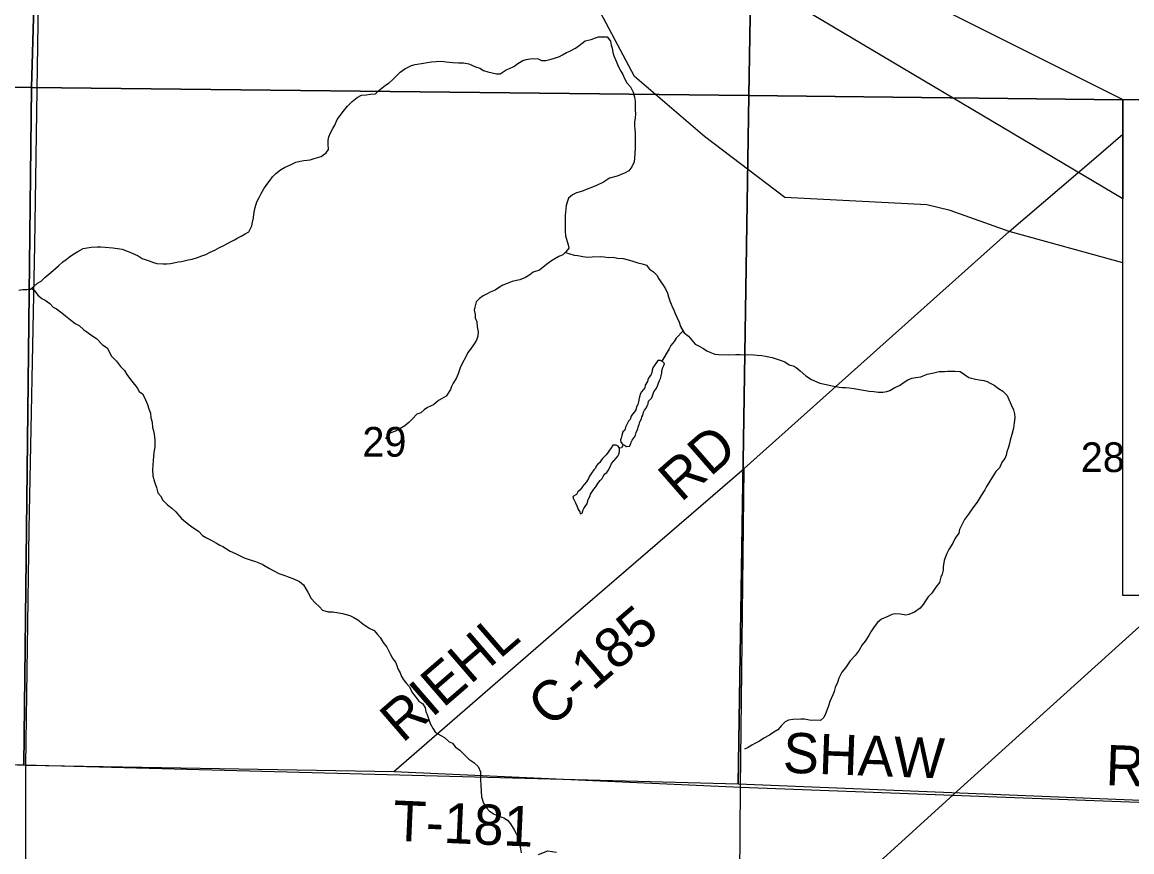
# Model space of a CAD drawing. Extents: x 0 to 34, y 0 to 22.
# Drawn here: x 26.932 to 28.499, y 14.843 to 16.014 of the extents above; entities that cross this region are included whole.
import ezdxf

# ---------------------------------------------------------------- set-up
doc = ezdxf.new("R2010")
doc.units = 0
for name, color, linetype in [('GM_X_County_Road', 7, 'Continuous'), ('GM_X_County_Road_Text', 7, 'Continuous'), ('GM_X_Minor_Lake', 7, 'Continuous'), ('GM_X_Minor_River', 7, 'Continuous'), ('GM_X_Rail_Line', 7, 'Continuous'), ('GM_X_Section', 7, 'Continuous'), ('GM_X_Section_Text', 7, 'Continuous'), ('GM_X_State_Route', 7, 'Continuous'), ('GM_X_Township_Road', 7, 'Continuous'), ('GM_X_Township_Road_Text', 7, 'Continuous'), ('SH_Data', 7, 'Continuous')]:
    doc.layers.add(name, color=color, linetype=linetype)

msp = doc.modelspace()

# ---------------------------------------------------------------- linework, layer by layer
at = {"layer": 'GM_X_County_Road'}
msp.add_line((26.9373, 14.9656), (27.457, 14.957), dxfattribs=at)
for points in [[(27.457, 14.957), (27.693, 15.1617), (27.9517, 15.3847), (28.3257, 15.7191), (28.4454, 15.8213), (28.4862, 15.8565)], [(25.9196, 14.987), (25.9277, 14.9881), (25.9453, 14.988), (26.0896, 14.9852), (26.5296, 14.9746), (26.8435, 14.9693), (26.9373, 14.9656)]]:
    msp.add_lwpolyline(points, dxfattribs=at)
at = {"layer": 'GM_X_Minor_Lake'}
for points in [[(27.8297, 15.5369), (27.8227, 15.5268), (27.8215, 15.5234), (27.8211, 15.52), (27.8199, 15.5162), (27.8171, 15.5128), (27.8156, 15.5098), (27.8151, 15.5072), (27.812, 15.5019), (27.8112, 15.4985), (27.8065, 15.4929), (27.8045, 15.4896), (27.8041, 15.4869), (27.8033, 15.4839), (27.8024, 15.4786), (27.8016, 15.4748), (27.7996, 15.4715), (27.7988, 15.4673), (27.7968, 15.4643), (27.7937, 15.4613), (27.7922, 15.4583), (27.7905, 15.4538), (27.7882, 15.4512), (27.7859, 15.4467), (27.7839, 15.4429), (27.783, 15.4388), (27.7803, 15.4362), (27.7787, 15.4309), (27.7779, 15.4275), (27.7771, 15.4249), (27.7774, 15.4215), (27.78, 15.4184), (27.7808, 15.4181)], [(27.7808, 15.4181), (27.7826, 15.4176), (27.7856, 15.4156), (27.7898, 15.4159), (27.7917, 15.4193), (27.7922, 15.4219), (27.7933, 15.4245), (27.7961, 15.4283), (27.798, 15.4317), (27.7992, 15.4351), (27.8012, 15.4403), (27.8021, 15.4433), (27.8033, 15.4467), (27.8041, 15.4505), (27.8065, 15.4546), (27.8069, 15.4573), (27.8085, 15.4599), (27.8093, 15.4641), (27.8109, 15.4667), (27.8132, 15.4697), (27.8148, 15.4731), (27.816, 15.4757), (27.8164, 15.4795), (27.8211, 15.4843), (27.8219, 15.4873), (27.8239, 15.4926), (27.827, 15.4963), (27.8294, 15.5005), (27.8302, 15.5039), (27.8322, 15.5087), (27.8334, 15.5114), (27.8342, 15.5152), (27.8351, 15.5197), (27.8355, 15.5223), (27.8367, 15.5269), (27.8383, 15.5299), (27.8391, 15.5329), (27.8365, 15.5352), (27.8332, 15.5368), (27.8297, 15.5369)], [(27.7663, 15.4175), (27.7636, 15.4138), (27.7616, 15.4104), (27.7585, 15.4063), (27.7566, 15.4037), (27.7515, 15.3984), (27.7492, 15.3955), (27.7476, 15.3928), (27.7449, 15.3906), (27.7426, 15.3876), (27.7414, 15.385), (27.7391, 15.3824), (27.736, 15.3779), (27.7332, 15.3738), (27.7316, 15.3704), (27.7289, 15.3655), (27.7258, 15.3618), (27.7231, 15.3592), (27.7219, 15.3566), (27.7196, 15.3539), (27.7169, 15.3517), (27.7149, 15.3476), (27.7095, 15.345), (27.7102, 15.3424), (27.7117, 15.3397), (27.7135, 15.3359), (27.7153, 15.332), (27.7164, 15.3293), (27.7171, 15.3267), (27.7193, 15.3232), (27.72, 15.3206), (27.7231, 15.322), (27.7239, 15.325), (27.7251, 15.328), (27.7278, 15.3322), (27.7298, 15.3348), (27.7314, 15.3408), (27.7334, 15.3449), (27.7346, 15.3483), (27.7393, 15.3551), (27.742, 15.3584), (27.7451, 15.3633), (27.7482, 15.3674), (27.751, 15.3704), (27.7525, 15.373), (27.7549, 15.3771), (27.7576, 15.379), (27.7595, 15.3816), (27.7627, 15.388), (27.7643, 15.3917), (27.7709, 15.3992), (27.7732, 15.4018), (27.7748, 15.4048), (27.7756, 15.4082), (27.7753, 15.413)], [(27.7753, 15.413), (27.7735, 15.4158), (27.7709, 15.4174), (27.7663, 15.4175)]]:
    msp.add_lwpolyline(points, dxfattribs=at)
at = {"layer": 'GM_X_Minor_River'}
for points in [[(27.2599, 15.7486), (27.2611, 15.7531), (27.2634, 15.7607), (27.2669, 15.7671), (27.2693, 15.7728), (27.2731, 15.7792), (27.2777, 15.7856), (27.282, 15.7916), (27.2855, 15.7961), (27.2904, 15.801), (27.2966, 15.8059), (27.3023, 15.8092), (27.3076, 15.8118), (27.3126, 15.8141), (27.3183, 15.8167), (27.3248, 15.8185), (27.3297, 15.8192), (27.3343, 15.8199), (27.3388, 15.8202), (27.3445, 15.8221), (27.3544, 15.825), (27.3613, 15.8303), (27.3648, 15.8348), (27.3641, 15.8424), (27.3642, 15.8481), (27.365, 15.8526), (27.3673, 15.8583), (27.3708, 15.8643), (27.3735, 15.8692), (27.3767, 15.8772), (27.387, 15.8907), (27.3913, 15.896), (27.3978, 15.9024), (27.4051, 15.9084), (27.4112, 15.9113), (27.418, 15.912), (27.4241, 15.9131), (27.4309, 15.9134), (27.4355, 15.9183), (27.4451, 15.9254), (27.4501, 15.9291), (27.4547, 15.9325), (27.46, 15.9381), (27.4658, 15.9438), (27.4723, 15.9486), (27.4773, 15.9512), (27.4818, 15.9535), (27.4872, 15.9546), (27.4986, 15.9567), (27.5039, 15.9578), (27.51, 15.9585), (27.5164, 15.9592), (27.524, 15.9595), (27.5308, 15.9586), (27.5403, 15.9578), (27.5483, 15.9573), (27.5551, 15.9572), (27.5627, 15.9556), (27.5721, 15.9517), (27.5785, 15.9494), (27.5834, 15.9463), (27.5895, 15.9443), (27.5959, 15.9431), (27.6019, 15.9416), (27.6072, 15.9415), (27.6157, 15.9471), (27.6202, 15.9493), (27.6263, 15.9519), (27.6321, 15.9564), (27.6389, 15.9605), (27.6439, 15.962), (27.6492, 15.9627), (27.6545, 15.9634), (27.6606, 15.9629), (27.6655, 15.9602), (27.6716, 15.9602), (27.6788, 15.9624), (27.6837, 15.9638), (27.6906, 15.966), (27.6952, 15.9686), (27.7009, 15.9716), (27.7055, 15.9738), (27.7135, 15.9779), (27.7185, 15.9817), (27.7269, 15.988), (27.7353, 15.9902), (27.7414, 15.9924), (27.7459, 15.9939), (27.7581, 15.9938), (27.7629, 15.9877), (27.7636, 15.9823), (27.7651, 15.9778), (27.7661, 15.9717), (27.7676, 15.9671), (27.7709, 15.9595), (27.7735, 15.9526), (27.7772, 15.9454), (27.7802, 15.9408), (27.7824, 15.9351), (27.7861, 15.9289), (27.791, 15.9232)], [(27.791, 15.9232), (27.7947, 15.9159), (27.7965, 15.9087), (27.7976, 15.903), (27.7975, 15.8954), (27.7978, 15.8901), (27.7982, 15.8852), (27.7977, 15.8795), (27.7969, 15.8734), (27.7968, 15.8681), (27.7972, 15.8635), (27.7975, 15.8575), (27.7978, 15.8525), (27.7977, 15.8411), (27.7976, 15.8366), (27.7972, 15.8297), (27.7967, 15.8225), (27.7963, 15.8176), (27.7931, 15.8104), (27.7885, 15.8048), (27.7836, 15.8018), (27.7721, 15.797), (27.7615, 15.7944), (27.7531, 15.7885), (27.7431, 15.784), (27.7351, 15.7807), (27.7283, 15.7785), (27.7233, 15.7759), (27.715, 15.7737), (27.7092, 15.7707), (27.7035, 15.7662), (27.7019, 15.7617), (27.7, 15.7556), (27.6987, 15.7416), (27.6986, 15.7336), (27.6989, 15.726), (27.6988, 15.7196), (27.6995, 15.7131), (27.7031, 15.7002), (27.7038, 15.6956), (27.7004, 15.6907), (27.6954, 15.6862), (27.69, 15.6836), (27.6843, 15.6806), (27.6782, 15.6765), (27.6725, 15.6724), (27.6625, 15.6645), (27.6538, 15.6616), (27.6488, 15.6579), (27.643, 15.6541), (27.635, 15.6508), (27.6301, 15.6497), (27.624, 15.6483), (27.6168, 15.6457), (27.6107, 15.6431), (27.6046, 15.6397), (27.6, 15.636), (27.5931, 15.6334), (27.5878, 15.6304), (27.5832, 15.6282), (27.5778, 15.6244), (27.5729, 15.6196), (27.5713, 15.6124), (27.5704, 15.6078), (27.5715, 15.6021), (27.5718, 15.5972), (27.5741, 15.5915), (27.5747, 15.5846), (27.5758, 15.5774), (27.5757, 15.5713), (27.5734, 15.5657), (27.5695, 15.5592), (27.5653, 15.5528), (27.5614, 15.5483), (27.5583, 15.5419), (27.5533, 15.5325), (27.5506, 15.5268), (27.5478, 15.5181), (27.5447, 15.5117), (27.5408, 15.5049), (27.5381, 15.5004), (27.5369, 15.4958), (27.5308, 15.4864), (27.5243, 15.4827), (27.5197, 15.4804), (27.5128, 15.4744), (27.5044, 15.4704), (27.4998, 15.4674), (27.4948, 15.4629), (27.4895, 15.461), (27.4826, 15.4539), (27.478, 15.4494), (27.4726, 15.4445), (27.4642, 15.44), (27.4593, 15.4374), (27.4524, 15.4348), (27.4478, 15.4311), (27.4451, 15.4266)], [(26.9271, 15.6364), (26.9328, 15.6371), (26.9388, 15.6374), (26.9438, 15.6377), (26.9491, 15.6418), (26.9537, 15.646), (26.9587, 15.649), (26.9641, 15.6542), (26.9698, 15.6587), (26.9756, 15.664), (26.9832, 15.6707), (26.9894, 15.676), (26.9939, 15.6793), (26.9989, 15.6831), (27.0035, 15.6864), (27.0104, 15.6909), (27.018, 15.695), (27.0294, 15.6968), (27.0378, 15.6975), (27.0431, 15.6974), (27.0491, 15.6969), (27.0598, 15.6961), (27.073, 15.694), (27.0817, 15.6909), (27.0862, 15.689), (27.096, 15.6847), (27.1013, 15.6808), (27.1115, 15.6777), (27.1176, 15.6753), (27.1221, 15.6741), (27.1312, 15.6733), (27.1361, 15.6732), (27.1414, 15.6739), (27.1464, 15.675), (27.1521, 15.6761), (27.157, 15.6768), (27.1665, 15.679), (27.1719, 15.6801), (27.1795, 15.6823), (27.1856, 15.6845), (27.1913, 15.6867), (27.1974, 15.6897), (27.2039, 15.6926), (27.2107, 15.6963), (27.2157, 15.6986), (27.221, 15.7016), (27.2271, 15.7049), (27.2317, 15.7075), (27.2367, 15.7101), (27.2413, 15.7123), (27.247, 15.7157), (27.2519, 15.7187), (27.2562, 15.727), (27.2574, 15.7323), (27.2586, 15.7384), (27.2591, 15.7433), (27.2599, 15.7486)], [(27.6991, 15.6896), (27.7117, 15.6857), (27.7166, 15.6852), (27.7238, 15.6836), (27.7302, 15.6828), (27.7371, 15.6831), (27.7485, 15.6837), (27.7541, 15.6833), (27.7602, 15.6825), (27.7667, 15.6828), (27.7727, 15.6816), (27.7807, 15.6807), (27.7897, 15.6787), (27.7943, 15.6772), (27.8015, 15.6748), (27.8075, 15.6736), (27.8136, 15.6713), (27.818, 15.6659), (27.8237, 15.6621), (27.8286, 15.6571), (27.8308, 15.6525), (27.8364, 15.6448), (27.8405, 15.6383), (27.8431, 15.6322), (27.8449, 15.6269), (27.8464, 15.6212), (27.8493, 15.6139), (27.8523, 15.6082), (27.8541, 15.6033), (27.8563, 15.5983), (27.8597, 15.5911), (27.8619, 15.585), (27.8667, 15.5762), (27.8731, 15.5712), (27.8825, 15.5601), (27.887, 15.5577), (27.8942, 15.5539), (27.8987, 15.5508), (27.9032, 15.5488), (27.91, 15.5461), (27.9153, 15.5453), (27.9293, 15.5451), (27.94, 15.5454), (27.9456, 15.5453), (27.9654, 15.5451), (27.9699, 15.5447), (27.9767, 15.5439), (27.9817, 15.5431), (27.9911, 15.5414), (27.9983, 15.5387), (28.004, 15.5371), (28.0089, 15.5352), (28.0153, 15.5309), (28.0206, 15.5294), (28.0251, 15.527), (28.0307, 15.5224), (28.0386, 15.5151), (28.0465, 15.5101), (28.0582, 15.505), (28.0696, 15.5026), (28.076, 15.5014), (28.0855, 15.4994), (28.09, 15.499), (28.0946, 15.4989), (28.0999, 15.4985), (28.1067, 15.4973), (28.1143, 15.4961), (28.1203, 15.4953), (28.1283, 15.4937), (28.1347, 15.4932), (28.1415, 15.4924), (28.1476, 15.4923), (28.1529, 15.4934), (28.1575, 15.4945), (28.1644, 15.4986), (28.1708, 15.5015), (28.1762, 15.5053), (28.1827, 15.5098), (28.1884, 15.512), (28.1941, 15.5131), (28.2009, 15.5141), (28.2101, 15.5178), (28.2192, 15.5196), (28.2268, 15.5214), (28.2344, 15.5214), (28.239, 15.5217), (28.2439, 15.522), (28.2492, 15.522), (28.2568, 15.5215), (28.2688, 15.513), (28.2783, 15.5106), (28.2832, 15.5098), (28.29, 15.5086), (28.2946, 15.5071), (28.2991, 15.5051), (28.3044, 15.502), (28.3108, 15.4974), (28.3168, 15.4935), (28.3228, 15.4874), (28.3254, 15.482), (28.3287, 15.4744)], [(26.9451, 15.6388), (26.9487, 15.6362), (26.9539, 15.6293), (26.9599, 15.6243), (26.9645, 15.6223), (26.9712, 15.6173), (26.9757, 15.6123), (26.9803, 15.61), (26.9882, 15.6042), (26.9934, 15.6), (27.0002, 15.5942), (27.007, 15.5892), (27.0126, 15.5865), (27.019, 15.5804), (27.0235, 15.5773), (27.0291, 15.573), (27.0371, 15.568), (27.0453, 15.5592), (27.0521, 15.5546), (27.058, 15.5431), (27.0651, 15.5358), (27.0707, 15.5285), (27.0764, 15.5228), (27.0797, 15.5171), (27.085, 15.5102), (27.0887, 15.5052), (27.0943, 15.4983), (27.0973, 15.4933), (27.1018, 15.4899), (27.1048, 15.4845), (27.1088, 15.475), (27.111, 15.4689), (27.1132, 15.4624), (27.1139, 15.456), (27.1154, 15.4499), (27.116, 15.4426), (27.1175, 15.4377), (27.1182, 15.4328), (27.1192, 15.4244), (27.1195, 15.4153), (27.1179, 15.4073), (27.117, 15.3963), (27.1166, 15.3887), (27.1161, 15.383), (27.1164, 15.3743), (27.119, 15.3659), (27.1215, 15.3579), (27.1237, 15.3503), (27.1275, 15.3457), (27.1308, 15.3396), (27.1372, 15.3331), (27.1432, 15.3285), (27.1488, 15.3235), (27.1571, 15.3139), (27.168, 15.305), (27.1744, 15.3004), (27.1811, 15.2958), (27.1868, 15.29), (27.1924, 15.2866), (27.1988, 15.2831), (27.2064, 15.2792), (27.2109, 15.2765), (27.2154, 15.2742), (27.2256, 15.2676), (27.2331, 15.2645), (27.2456, 15.2583), (27.2569, 15.2547), (27.2614, 15.2532), (27.2709, 15.2493), (27.2814, 15.2435), (27.2943, 15.2365), (27.3029, 15.2334), (27.3075, 15.2318), (27.3143, 15.2291), (27.3237, 15.2248), (27.3293, 15.2205), (27.3327, 15.2144), (27.3353, 15.2099), (27.3401, 15.2011), (27.3457, 15.1949), (27.3517, 15.1892), (27.3562, 15.1846), (27.3642, 15.1822), (27.3706, 15.1821), (27.3843, 15.1797), (27.3896, 15.1785), (27.3945, 15.1769), (27.4005, 15.1742), (27.4062, 15.1708), (27.4133, 15.1654), (27.422, 15.1592), (27.4291, 15.1557), (27.434, 15.1503), (27.4377, 15.1457), (27.4418, 15.1389), (27.4471, 15.1323), (27.4493, 15.1274), (27.4523, 15.122), (27.4556, 15.1159), (27.459, 15.111), (27.4612, 15.1064)], [(27.8652, 15.5789), (27.8556, 15.5683), (27.8525, 15.5638), (27.8479, 15.5582), (27.8456, 15.5532), (27.8352, 15.5359)], [(28.3287, 15.4744), (28.3317, 15.4672), (28.3335, 15.4618), (28.3338, 15.4558), (28.333, 15.4489), (28.3317, 15.4414), (28.3294, 15.4327), (28.3274, 15.4247), (28.3262, 15.4198), (28.325, 15.4145), (28.3226, 15.4081), (28.3214, 15.4031), (28.3195, 15.3986), (28.316, 15.3937), (28.3121, 15.3854), (28.3068, 15.3801), (28.3021, 15.3726), (28.2971, 15.3643), (28.294, 15.359), (28.2913, 15.3545), (28.2863, 15.3462), (28.2805, 15.3371), (28.2743, 15.3288), (28.2682, 15.3198), (28.2628, 15.3123), (28.2593, 15.3059), (28.2558, 15.2983), (28.2549, 15.293), (28.2496, 15.2862), (28.2461, 15.279), (28.2407, 15.27), (28.2379, 15.2643), (28.236, 15.2598), (28.234, 15.2545), (28.2328, 15.2458), (28.2324, 15.2412), (28.2312, 15.2355), (28.2292, 15.231), (28.2272, 15.2238), (28.2222, 15.217), (28.2168, 15.2084), (28.2114, 15.2035), (28.2076, 15.1978), (28.2045, 15.1926), (28.1999, 15.1873), (28.1922, 15.1817), (28.1842, 15.1783), (28.1797, 15.1776), (28.1725, 15.1789), (28.1649, 15.1793), (28.16, 15.1782), (28.1546, 15.1756), (28.1455, 15.1719), (28.1397, 15.1671), (28.1351, 15.161), (28.1305, 15.1539), (28.1278, 15.1486), (28.1224, 15.1407), (28.1181, 15.1358), (28.1139, 15.1282), (28.1081, 15.1207), (28.1012, 15.1128), (28.0946, 15.103), (28.0896, 15.097), (28.0853, 15.0883), (28.0834, 15.0826), (28.0803, 15.0754), (28.0787, 15.0698), (28.0767, 15.0652), (28.0725, 15.0558), (28.0705, 15.0494), (28.0689, 15.0444), (28.0666, 15.038), (28.0642, 15.0331), (28.0592, 15.0286), (28.0505, 15.0291), (28.046, 15.0287), (28.0369, 15.0307), (28.0316, 15.0308), (28.0202, 15.0302), (28.0141, 15.0291), (28.0095, 15.0269), (28.0045, 15.0216), (27.9992, 15.0156), (27.9934, 15.0122), (27.9873, 15.0081), (27.9793, 15.0036), (27.9732, 14.9995), (27.9678, 14.9966), (27.9625, 14.994), (27.9572, 14.9906), (27.9522, 14.9884)], [(27.7808, 15.4181), (27.7784, 15.4138), (27.7753, 15.413)], [(27.4612, 15.1064), (27.4627, 15.1018), (27.4656, 15.0961), (27.4675, 15.0908), (27.4708, 15.0858), (27.4746, 15.0812), (27.4787, 15.0766), (27.4831, 15.0678), (27.488, 15.0617), (27.4921, 15.0559), (27.4977, 15.0521), (27.5011, 15.0467), (27.5022, 15.0414), (27.5044, 15.0357), (27.5062, 15.0304), (27.5081, 15.0246), (27.5125, 15.017), (27.5155, 15.0117), (27.5234, 15.0078), (27.5283, 15.0047), (27.5351, 14.9985), (27.5396, 14.997), (27.5433, 14.9916), (27.5501, 14.987), (27.5572, 14.9797), (27.5629, 14.9743), (27.57, 14.9697), (27.576, 14.9636), (27.579, 14.9563), (27.5792, 14.9453), (27.5799, 14.9369), (27.5802, 14.929), (27.5808, 14.921), (27.5834, 14.9122), (27.5875, 14.9057), (27.5916, 14.9011), (27.5984, 14.8965), (27.6078, 14.8926), (27.6124, 14.8914), (27.6173, 14.8879), (27.6214, 14.883), (27.6266, 14.8746), (27.6303, 14.8681), (27.6329, 14.8627), (27.634, 14.8582), (27.6347, 14.8521), (27.6358, 14.8475), (27.6368, 14.8418)], [(27.6611, 14.8396), (27.6744, 14.8448), (27.6865, 14.8428)]]:
    msp.add_lwpolyline(points, dxfattribs=at)
at = {"layer": 'GM_X_Rail_Line'}
msp.add_lwpolyline([(27.3262, 14.1), (27.337, 14.1097), (27.6409, 14.3774), (27.9444, 14.6491), (28.2526, 14.9288), (28.5584, 15.2053)], dxfattribs=at)
at = {"layer": 'GM_X_Section'}
for points in [[(26.974, 16.9197), (26.945, 15.9224), (25.9635, 15.9304), (25.9861, 16.8906), (25.9875, 16.9239)], [(27.9749, 16.9131), (27.9584, 15.9108), (26.945, 15.9224), (26.974, 16.9197)], [(26.945, 15.9224), (26.9342, 14.9655), (25.9137, 14.9847), (25.9617, 15.8807), (25.9635, 15.9304)], [(27.9584, 15.9108), (27.9429, 14.9391), (26.9342, 14.9655), (26.945, 15.9224)]]:
    msp.add_lwpolyline(points, close=True, dxfattribs=at)
for points in [[(28.4862, 15.9049), (27.9584, 15.9108), (27.9749, 16.9131), (28.9846, 16.9148), (28.9715, 15.9053)], [(28.966, 15.2053), (28.9636, 14.8975), (27.9429, 14.9391), (27.9584, 15.9108), (28.4862, 15.9049)]]:
    msp.add_lwpolyline(points, dxfattribs=at)
at = {"layer": 'GM_X_State_Route'}
msp.add_lwpolyline([(26.9378, 14.6458), (26.9373, 14.9656), (26.9419, 15.2988), (26.9497, 15.6998), (26.956, 16.1074)], dxfattribs=at)
at = {"layer": 'GM_X_Township_Road'}
for p, q in [((27.9464, 14.9347), (27.9517, 15.3847)), ((27.9387, 14.1), (27.9464, 14.9347))]:
    msp.add_line(p, q, dxfattribs=at)
for points in [[(28.4862, 15.6748), (28.3257, 15.7191), (28.2426, 15.7489), (28.2094, 15.7567), (28.0091, 15.7671), (27.8954, 15.8533), (27.7969, 15.9377), (27.7527, 16.0204), (27.7055, 16.1036), (27.703, 16.1424), (27.7027, 16.2161)], [(27.457, 14.957), (27.9464, 14.9347), (29.4075, 14.8797)]]:
    msp.add_lwpolyline(points, dxfattribs=at)
at = {"layer": 'SH_Data'}
for points in [[(26.9862, 16.6553), (28.4862, 15.9053), (28.4862, 15.7653)], [(28.4862, 15.9053), (30.0249, 15.9053), (30.0249, 15.2053), (28.4862, 15.2053)]]:
    msp.add_lwpolyline(points, close=True, dxfattribs=at)

# ---------------------------------------------------------------- texts
at = {"layer": 'GM_X_County_Road_Text'}
for s, rotation, p in [('RD', 41.14, (27.8623, 15.3358)), ('C-185', 40.7203, (27.6776, 15.0172)), ('RIEHL', 40.8551, (27.469, 14.9959))]:
    msp.add_text(s, height=0.05682, rotation=rotation, dxfattribs=at).set_placement(p)
at = {"layer": 'GM_X_Section_Text'}
for s, p in [('29', (27.4124, 15.4012)), ('28', (28.4269, 15.3795))]:
    msp.add_text(s, height=0.04186, rotation=0, dxfattribs=at).set_placement(p)
at = {"layer": 'GM_X_Township_Road_Text'}
for s, rotation, p in [('SHAW', 357.8965, (28.0057, 14.9552)), ('RD', 358.0252, (28.4615, 14.9376)), ('T-181', 357.4736, (27.4547, 14.8593))]:
    msp.add_text(s, height=0.05682, rotation=rotation, dxfattribs=at).set_placement(p)

doc.saveas('drawing.dxf')
